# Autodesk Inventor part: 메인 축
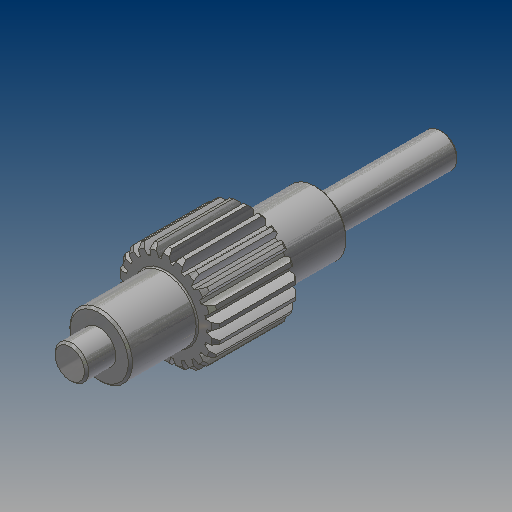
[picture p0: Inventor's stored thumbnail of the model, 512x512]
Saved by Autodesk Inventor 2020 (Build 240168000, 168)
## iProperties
CustomPartVersion: 1
Created: 2016-02
Part Number: 메인 축
Material: 강철, 연강
Document SubType Name: Modeling
Categories: <?xml version="1.0" encoding="UTF-16"?> <MemberInstance><Categories><FamilyTemplate><FamilyTemplateParameter ValueType="xs:double" Id="1" ObjectReferenceKey="da
Density: 7.86 g/cm^3
Appearance: 강철
Author: mdu
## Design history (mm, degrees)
sketch "Sketch1"
  geometry: C1 r 12 at (0, 0)
  constraints: 1 centre point
  dimensions: "d0" = 24 diameter of C1 (= da_da)
extrude "Extrusion1" new body sketch "Sketch1" distance "d1" = 20 (= da_b); taper "d2" = 0 deg
workplane "Work Plane2"
feature "피치 지름" dims "d4" = 10, "d5" = 0
workplane "Work Plane8"
workplane "Work Plane9"
chamfer "모따기1" distance "d49" = 1; stored, may be unused: second distance "d50" = 2, angle "d51" = 45 deg
sketch "스케치3"
  geometry: C1 r 7.5 at (0, 0); 1 further point
  constraints: 1 centre point, 1 coincident
  dimensions: "d52" = 15 diameter of C1
extrude "돌출2" join sketch "스케치3" distance "d53" = 16; taper "d54" = 0 deg
sketch "스케치4"
  geometry: C1 r 4 at (0, 0); 1 further point
  constraints: 1 centre point, 1 coincident
  dimensions: "d55" = 8 diameter of C1
extrude "돌출3" join sketch "스케치4" distance "d56" = 7; taper "d57" = 0 deg
sketch "스케치5"
  geometry: C1 r 7.5 at (0, 0) reference; C2 r 7.5 at (0, 0) reference; 1 further point
extrude "돌출4" join sketch "스케치5" distance "d62" = 16; taper "d63" = 0 deg
sketch "스케치6"
  geometry: C1 r 4 at (0, 0); 1 further point
  constraints: 1 centre point, 1 coincident
  dimensions: "d64" = 8 diameter of C1
extrude "돌출5" join sketch "스케치6" distance "d65" = 30; taper "d66" = 0 deg
chamfer "모따기2" distance "d58" = 0.5; stored, may be unused: second distance "d59" = 2, angle "d60" = 45 deg
fillet "모깎기1" dims "d61" = 0.3
feature "스퍼 기어" dims "da_b" = 20, "da_d" = 22, "da_aw" = 31, "da_da" = 24, "da_df" = 19.5, "da_dw" = 22, angle "da_beta" = 0 deg, "da_lefttooth" = 0, "da_righttooth" = 0
body "Solid1"
sketch "Sketch2"
  geometry: C1 r 12 at (0, 0) reference; C2 r 11 at (0, 0)
  constraints: 1 centre point, 1 coincident
  dimensions: "d3" = 22 diameter of C2 (= da_dw)
body "Srf1"
node "투영된 루프1"
other parameters: "d16" = 31 (= da_aw), "d17" = 0, "d34" = 1.428 (computed from da_z), "d39" = 0, "d41" = 0, "d43" = 31 (= da_aw), "d46" = 31 (= da_aw), "d47" = 0, "d48" = 0
